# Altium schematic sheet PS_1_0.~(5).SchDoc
size A4
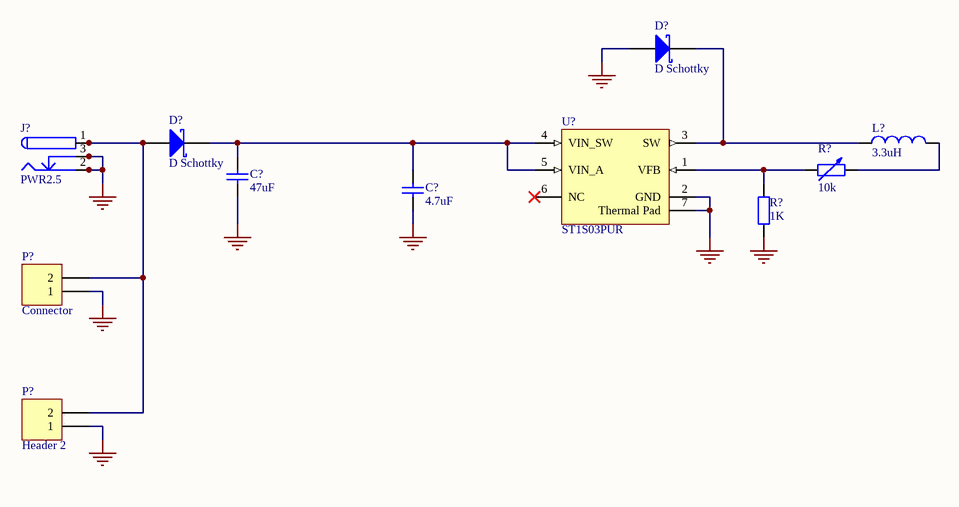
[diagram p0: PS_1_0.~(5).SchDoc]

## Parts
(Parts that share a designator on the sheet are numbered #1, #2 ... from top to bottom, then left to right.)
C?#1  47uF  [C0805]
C?#2  4.7uF  [C0805]
D?#1  D Schottky  [SMB]
D?#2  D Schottky  [SMB]
J?  PWR2.5  [KLD-0202]
L?  3.3uH  [0402-A]
P?#1  Connector  [L_ZAC]
P?#2  Header 2  [HDR1X2]
R?#1  10k  [AXIAL-0.6]
R?#2  1K  [0603]
U?  ST1S03PUR  [DFN6D_M]

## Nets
GND: C?#1.2 C?#2.2 D?#1.1(A) J?.2 J?.2A J?.2B J?.3 J?.3A J?.3B P?#1.1 P?#2.1 R?#2.1 U?.2(GND) U?.7(Thermal_Pad)
NetC?#1_1: C?#1.1 C?#2.1 D?#2.2(K) U?.4(VIN_SW) U?.5(VIN_A)
NetD?#1_2: D?#1.2(K) L?.1 U?.3(SW)
NetD?#2_1: D?#2.1(A) J?.1 J?.1A J?.1B P?#1.2 P?#2.2
NetL?_2: L?.2 R?#1.2
NetR?#1_1: R?#1.1 R?#2.2 U?.1(VFB)

Not connected (* = marked no-connect by the designer): U? 6(NC)*

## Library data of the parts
C?#1 C?#2 = Cap Semi: Capacitor (Semiconductor SIM Model)
D?#1 D?#2 = D Schottky: Schottky Diode
J? = PWR2.5: Low Voltage Power Supply Connector
L? = Inductor: Code_IEC: 1005
P?#1 P?#2 = Header 2: Header, 2-Pin
R?#1 = Res Adj2: Variable Resistor; Set Position: 0.5
R?#2 = Res2: Resistor
U? = ST1S03PUR: 1.5 A, 1.5 MHz adjustable, step-down switching regulator, DFN6D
